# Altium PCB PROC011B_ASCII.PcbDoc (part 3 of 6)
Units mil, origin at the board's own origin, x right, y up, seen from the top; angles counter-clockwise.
Board outline 3304 x 2569 mil, 6 copper layers (TOP, L2-GND1, L3-GND/SIG, L4-GND/SIG, L5-GND2, BOTTOM), stack 55.77 mil thick; 376 components, 289 nets, 1284 pads, 1755 vias.
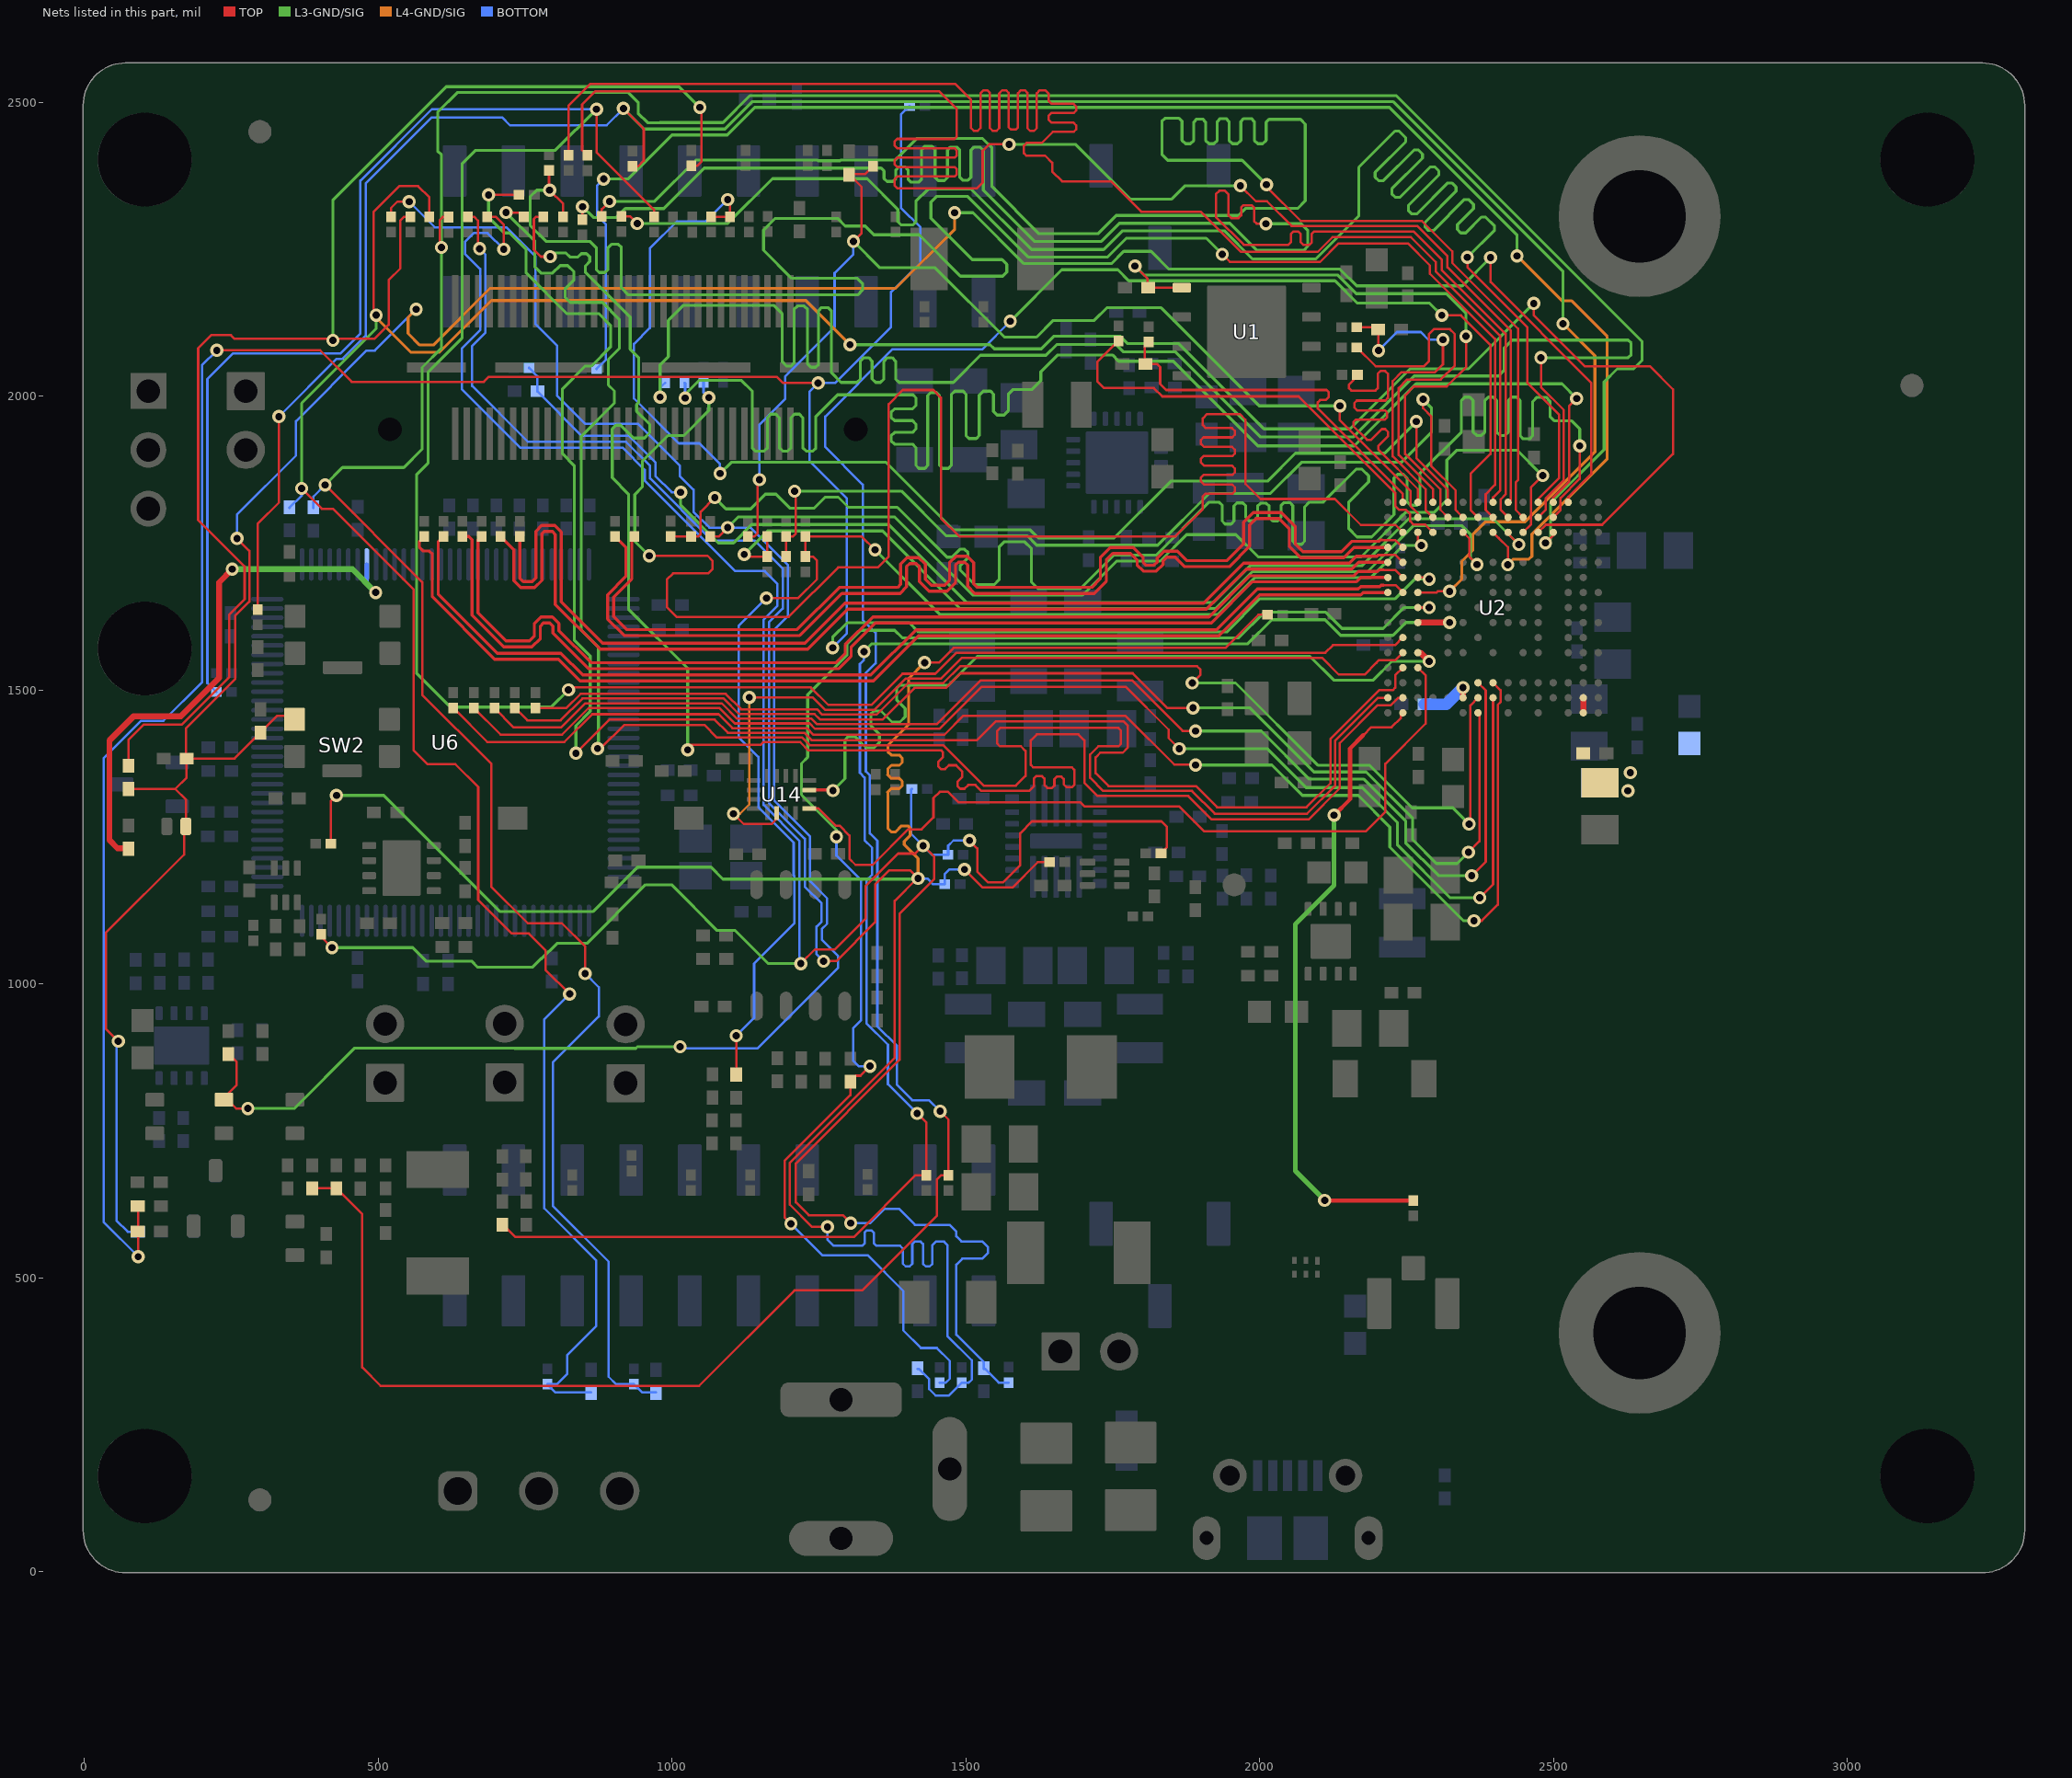
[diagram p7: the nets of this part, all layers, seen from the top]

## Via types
v1: diameter 22.4, hole 12.2, TOP to BOTTOM, tented both sides, 1046 vias
v2: diameter 15.74, hole 5.9, TOP to L2-GND1, tented both sides, 700 vias
v3: diameter 19.68, hole 7.87, TOP to BOTTOM, tented both sides, 9 vias

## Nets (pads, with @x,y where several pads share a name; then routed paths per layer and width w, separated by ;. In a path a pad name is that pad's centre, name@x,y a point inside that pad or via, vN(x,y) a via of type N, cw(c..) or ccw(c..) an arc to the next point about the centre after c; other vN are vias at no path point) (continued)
AR_DMM_SYNC: R55.1 U2.N14 | length 3163.6
  TOP w4: v1(961.35,1728.5) 1060.35,1728.5 1068.85,1720 1068.85,1705.6 1061.75,1698.5 1001.85,1698.5 991.45,1688.1 991.45,1640.9 1007.85,1624.5 1198.75,1624.5 1282.85,1708.6 1350.05,1708.6 1368.75,1727.3 1368.75,1986.5 1392.75,2010.5 1444.75,2010.5 1457.75,1997.5 1457.75,1792.5 1488.85,1761.4 1856.65,1761.4 1903.25,1808 1903.25,1829.61 1907.54,1833.9 1953.46,1833.9 1957.95,1838.39 1957.95,1845.01 1953.06,1849.9 1905.34,1849.9 1900.25,1854.99 1900.25,1861.61 1904.54,1865.9 1953.46,1865.9 1957.95,1870.39 1957.95,1877.01 1953.06,1881.9 1905.34,1881.9 1900.25,1886.99 1900.25,1893.61 1904.54,1897.9 1953.46,1897.9 1957.95,1902.39 1957.95,1909.01 1953.06,1913.9 1905.34,1913.9 1900.25,1918.99 1900.25,1925.61 1904.54,1929.9 1953.46,1929.9 1957.95,1934.39 1957.95,1941.01 1953.06,1945.9 1908.34,1945.9 1903.25,1950.99 1903.25,1962 1910.75,1969.5 1966.55,1969.5 1975.95,1960.1 1975.95,1850.9 2001.75,1825.1 2128.16,1825.1 2172.36,1780.9 2231.21,1780.9 U2.N14@2243.76,1768.35
  L3-GND/SIG w5: v1(961.35,1728.5) 936.75,1753.1 936.75,1832.8 949.65,1845.7 949.65,1889.7 992.95,1933 1020.15,1933 1062.75,1975.6 v1(1062.75,1997.5)
  BOTTOM w4: R55.1@1053.75,2023.31 1053.75,2006.5 v1(1062.75,1997.5)
AR_DP0: R56.1 U2.R4 | length 3155.8
  TOP w4: U2.R4@2499.66,1819.53 2499.66,1827.31 2526.95,1854.6 2526.95,1983.6 v1(2539.55,1996.2)
  L3-GND/SIG w5: v1(1022.45,1997) 1022.45,2002.96 1046.67,2027.18 1117.7,2027.18 1136.75,2008.13 1136.75,1911.51 1141.76,1906.5 1156.74,1906.5 1162.6,1912.36 1162.6,1963.64 1168.46,1969.5 1176.74,1969.5 1182.6,1963.64 1182.6,1912.36 1188.46,1906.5 1196.74,1906.5 1202.6,1912.36 1202.6,1963.64 1208.46,1969.5 1216.74,1969.5 1222.6,1963.64 1222.6,1912.36 1228.46,1906.5 1239.75,1906.5 1244.75,1911.5 1244.75,1965.4 1281.65,2002.3 1410.29,2002.3 1415.29,1997.3 1415.29,1984.27 1409.43,1978.41 1378.61,1978.41 1372.75,1972.55 1372.75,1964.27 1378.61,1958.41 1409.43,1958.41 1415.29,1952.55 1415.29,1944.27 1409.43,1938.41 1378.61,1938.41 1372.75,1932.55 1372.75,1924.27 1378.61,1918.41 1409.43,1918.41 1415.29,1912.55 1415.29,1882.23 1420.29,1877.23 1430.29,1877.23 1435.29,1882.23 1435.29,2001.2 1440.29,2006.2 1450.29,2006.2 1455.29,2001.2 1455.29,1882.23 1460.29,1877.23 1470.29,1877.23 1475.29,1882.23 1475.29,2002.64 1481.15,2008.5 1495.35,2008.5 1500.35,2003.5 1500.35,1933.06 1505.35,1928.06 1517.95,1928.06 1522.95,1933.06 1522.95,2001.7 1529.75,2008.5 1542.25,2008.5 1547.25,2003.5 1547.25,1973.9 1553.15,1968 1565.25,1968 1572.35,1975.1 1572.35,2003.1 1580.75,2011.5 1612.75,2011.5 1627.75,2026.5 1627.75,2041.5 1656.35,2070.1 1749.55,2070.1 1760.15,2059.5 1852.95,2059.5 1996.95,1915.5 2160.95,1915.5 2266.55,2021.1 2514.65,2021.1 v1(2539.55,1996.2)
  BOTTOM w4: R56.1@1021.25,2022.81 1022.45,2021.61 v1(1022.45,1997)
AR_DP1: R57.1 U2.P5 | length 3113.8
  TOP w4: U2.P5@2474.07,1793.94 2486.75,1806.62 2486.75,1826 2517.75,1857 2517.75,1976.5 2478.75,2015.5 v1(2478.75,2065.5)
  L3-GND/SIG w5: v1(979.75,1998.5) 979.75,2053.5 993.75,2067.5 993.75,2128.84 1019.51,2154.6 1172.96,2154.6 1187.72,2139.84 1187.72,2058.36 1194.88,2051.2 1202.72,2051.2 1207.72,2056.2 1207.72,2147.76 1213.54,2153.58 1224.94,2153.58 1230.74,2147.78 1230.74,2055.06 1236.6,2049.2 1244.44,2049.2 1249.44,2054.2 1249.44,2145.78 1254.44,2150.78 1265.65,2150.78 1271.45,2144.98 1271.45,2039.81 1287.76,2023.5 1314.75,2023.5 1320.61,2029.36 1320.61,2059.64 1326.47,2065.5 1334.75,2065.5 1340.61,2059.64 1340.61,2029.36 1346.47,2023.5 1354.75,2023.5 1360.61,2029.36 1360.61,2059.64 1366.47,2065.5 1374.75,2065.5 1380.61,2059.64 1380.61,2029.36 1386.47,2023.5 1478.75,2023.5 1524.75,2069.5 1636.35,2069.5 1654.75,2087.9 1756.15,2087.9 1768.65,2075.4 1856.95,2075.4 2001.85,1930.5 2159.05,1930.5 2263.05,2034.5 2406.75,2034.5 2415.95,2043.7 2415.95,2081.6 2429.85,2095.5 2627.25,2095.5 2632.25,2090.5 2632.25,2070.5 2627.25,2065.5 v1(2478.75,2065.5)
  BOTTOM w4: v1(979.75,1998.5) 979.75,2014.21 R57.1@988.35,2022.81
AR_DP2: R179.1 U2.R5 | length 3176.7
  TOP w4: R179.1@913.75,2305.99 928.76,2305.99 v1(940.85,2293.9) ; v1(2353.55,2236.2) 2353.55,2219.3 2455.75,2117.1 2455.75,2022.5 2509.75,1968.5 2509.75,1861 2474.07,1825.32 U2.R5@2474.07,1819.53
  L3-GND/SIG w5: v1(940.85,2293.9) 1094.95,2293.9 1171.05,2370 1332.25,2370 1384.35,2317.9 1384.35,2296.9 1389.75,2291.5 1410.15,2291.5 1415.15,2296.5 1415.15,2331.7 1435.75,2352.3 1509.15,2352.3 1611.95,2249.5 1734.75,2249.5 1766.75,2281.5 1939.95,2281.5 1987.95,2233.5 2095.75,2233.5 2168.75,2306.5 2168.75,2389.5 2230.41,2451.16 2237.49,2451.16 2248.64,2440.01 2248.64,2432.93 2196.62,2380.91 2196.62,2372.63 2202.49,2366.76 2210.77,2366.76 2263.09,2419.08 2270.17,2419.08 2277.24,2412.01 2277.24,2404.93 2224.92,2352.61 2224.92,2344.33 2230.79,2338.46 2239.07,2338.46 2290.89,2390.28 2297.97,2390.28 2305.04,2383.21 2305.04,2376.13 2253.22,2324.31 2253.22,2316.03 2259.09,2310.16 2267.37,2310.16 2320.04,2362.83 2327.12,2362.83 2334.19,2355.76 2334.19,2348.68 2281.52,2296.01 2281.52,2287.73 2287.39,2281.86 2295.67,2281.86 2348.54,2334.73 2355.62,2334.73 2363.92,2326.43 2363.92,2319.35 2336.55,2291.98 2336.55,2283.7 2342.42,2277.83 2350.7,2277.83 2377.57,2304.7 2384.65,2304.7 2399.81,2289.54 2399.81,2282.46 v1(2353.55,2236.2)
AR_DP3: R180.1 U2.P6 | length 3185.5
  TOP w4: R180.1@880.45,2306.19 880.45,2318.2 v1(893.75,2331.5) ; v1(2011.75,2359.9) 2011.75,2356.5 2070.15,2298.1 2276.15,2298.1 2328.05,2246.2 2328.05,2226.7 2439.75,2115 2439.75,1857.5 2435.75,1853.5 2435.75,1806.67 U2.P6@2448.48,1793.94
  L3-GND/SIG w5: v1(893.75,2331.5) 970.25,2331.5 1040.45,2401.7 1247.75,2401.7 1248.76,2400.69 1285.8,2400.69 1286.81,2401.7 1379.55,2401.7 1416.35,2438.5 1528.75,2438.5 1544.45,2422.8 1544.45,2356.6 1624.65,2276.4 1724.65,2276.4 1755.75,2307.5 1963.75,2307.5 1975.75,2319.5 2064.75,2319.5 2077.75,2332.5 2077.75,2462.9 2069.55,2471.1 2016.07,2471.1 2011.07,2466.1 2011.07,2435.36 2005.21,2429.5 1996.93,2429.5 1991.07,2435.36 1991.07,2467.4 1986.07,2472.4 1973.02,2472.4 1968.02,2467.4 1968.02,2435.36 1962.16,2429.5 1953.88,2429.5 1948.02,2435.36 1948.02,2467.4 1943.02,2472.4 1933.02,2472.4 1928.02,2467.4 1928.02,2435.36 1922.16,2429.5 1913.88,2429.5 1908.02,2435.36 1908.02,2466.6 1903.02,2471.6 1893.02,2471.6 1888.02,2466.6 1888.02,2435.36 1882.16,2429.5 1873.88,2429.5 1868.02,2435.36 1868.02,2467.9 1863.02,2472.9 1838.75,2472.9 1833.75,2467.9 1833.75,2411.5 1843.75,2401.5 1970.15,2401.5 v1(2011.75,2359.9)
AR_DP4: R181.1 U2.R7 | length 2953.5
  TOP w4: R181.1@856.25,2409.79 847.15,2418.89 847.15,2496.5 869.65,2519 1454.08,2519 1484.75,2488.33 1484.75,2441.81 1480.75,2437.81 1383.44,2437.81 1378.75,2433.12 1378.75,2426.5 1383.44,2421.81 1480.74,2421.81 1484.75,2417.8 1484.75,2409.81 1480.75,2405.81 1383.44,2405.81 1378.75,2401.12 1378.75,2394.5 1383.44,2389.81 1480.74,2389.81 1484.75,2385.8 1484.75,2377.81 1480.75,2373.81 1383.44,2373.81 1378.75,2369.12 1378.75,2358.5 1383.75,2353.5 1518.75,2353.5 1528.75,2363.5 1528.75,2417.5 1539.75,2428.5 v1(1573.75,2428.5) ; v1(1967.25,2358.2) 1993.65,2331.8 2012.45,2331.8 2054.45,2289.8 2268.45,2289.8 2319.75,2238.5 2319.75,2219.5 2427.75,2111.5 2427.75,1824.39 U2.R7@2422.89,1819.53
  L3-GND/SIG w5: v1(1573.75,2428.5) 1686.32,2428.5 1779.32,2335.5 1850.45,2335.5 1873.15,2358.2 v1(1967.25,2358.2)
AR_DP5: R182.1 U2.P7 | length 3035.8
  TOP w4: R182.1@847.75,2300.49 v1(847.75,2322.5) ; v1(2010.75,2293.5) 1994.75,2293.5 1990.75,2297.5 1990.75,2320.9 1986.75,2324.9 1972.75,2324.9 1968.75,2320.9 1968.75,2307.6 1964.05,2302.9 1951.95,2302.9 1946.75,2308.1 1946.75,2343.7 1940.85,2349.6 1931.65,2349.6 1925.75,2343.7 1925.75,2304.9 1973.15,2257.5 2048.95,2257.5 2053.64,2262.19 2053.64,2276.3 2057.64,2280.3 2065.64,2280.3 2069.64,2276.3 2069.64,2262.19 2074.33,2257.5 2084.75,2257.5 2088.75,2261.5 2088.75,2276.4 2092.75,2280.4 2261.85,2280.4 2309.75,2232.5 2309.75,2215.1 2418.75,2106.1 2418.75,1833.1 2410.35,1824.7 2410.35,1806.48 U2.P7@2422.89,1793.94
  L3-GND/SIG w5: v1(847.75,2322.5) 866.15,2304.1 905.35,2304.1 920.55,2319.3 986.05,2319.3 1054.95,2388.2 1355.89,2388.2 1360.89,2383.2 1360.89,2370.3 1365.89,2365.3 1375.89,2365.3 1380.89,2370.3 1380.89,2385 1385.89,2390 1396.75,2390 1401.75,2385 1401.75,2369.1 1406.75,2364.1 1419.75,2364.1 1424.75,2369.1 1424.75,2419.9 1429.75,2424.9 1442.75,2424.9 1447.75,2419.9 1447.75,2372.5 1453.25,2367 1463.75,2367 1468.75,2372 1468.75,2418.8 1473.75,2423.8 1484.75,2423.8 1489.75,2418.8 1489.75,2372.6 1494.75,2367.6 1503.75,2367.6 1508.75,2372.6 1508.75,2418.5 1513.75,2423.5 1524.75,2423.5 1529.75,2418.5 1529.75,2350.5 1616.75,2263.5 1730.75,2263.5 1761.55,2294.3 1949.35,2294.3 1995.35,2248.3 2075.41,2248.3 2081.75,2254.64 2081.75,2282.36 2070.61,2293.5 v1(2010.75,2293.5)
AR_DP6: R183.1 U2.R8 | length 2986.4
  TOP w4: R183.1@823.75,2410.19 823.75,2494.2 861.05,2531.5 1481.76,2531.5 1508.89,2504.37 1508.89,2456.19 1513.58,2451.5 1520.2,2451.5 1524.89,2456.19 1524.89,2515.31 1529.98,2520.4 1536.6,2520.4 1540.89,2516.11 1540.89,2456.19 1545.58,2451.5 1552.2,2451.5 1556.89,2456.19 1556.89,2515.31 1561.98,2520.4 1568.6,2520.4 1572.89,2516.11 1572.89,2457.5 1576.89,2453.5 1584.89,2453.5 1588.89,2457.5 1588.89,2515.31 1593.98,2520.4 1600.6,2520.4 1604.89,2516.11 1604.89,2456.19 1609.58,2451.5 1616.2,2451.5 1620.89,2456.19 1620.89,2515.31 1625.98,2520.4 1635.35,2520.4 1640.75,2515 1640.75,2502.6 1645.44,2497.91 1682.76,2497.91 1687.95,2492.72 1687.95,2486.1 1683.76,2481.91 1645.44,2481.91 1640.75,2477.22 1640.75,2470.6 1645.44,2465.91 1682.76,2465.91 1687.95,2460.72 1687.95,2454.1 1683.76,2449.91 1648.15,2449.91 1629.41,2431.17 1603.76,2431.17 1598.85,2426.26 1598.85,2413.2 1602.85,2409.2 1634.95,2409.2 1646.95,2397.2 1646.95,2382.5 1663.85,2365.6 1746.75,2365.6 1798.35,2314 1899.75,2314 1968.25,2245.5 2098.75,2245.5 2123.85,2270.6 2257.65,2270.6 2299.75,2228.5 2299.75,2212.2 2409.75,2102.2 2409.75,1840.1 2397.3,1827.65 U2.R8@2397.3,1819.53
AR_DP7: R60.2 R184.1 U2.P8 | length 3263.4
  TOP w4: R60.2@790.75,2384.51 790.75,2351.5 v1(791.75,2350.5) 814.75,2327.5 R184.1@814.75,2305.49 ; v1(1936.55,2241.4) 1949.45,2228.5 2102.75,2228.5 2134.25,2260 2252.25,2260 2289.75,2222.5 2289.75,2208.5 2400.75,2097.5 2400.75,1849.16 2384.8,1833.21 2384.8,1806.44 U2.P8@2397.3,1793.94
  L3-GND/SIG w5: v1(791.75,2350.5) 769.75,2350.5 758.75,2339.5 758.75,2290.5 785.75,2263.5 860.29,2263.5 871.15,2252.64 871.15,2215.6 876.15,2210.6 886.15,2210.6 891.15,2215.6 891.15,2252.64 897.01,2258.5 908.75,2258.5 913.75,2253.5 913.75,2184.5 925.85,2172.4 1316.05,2172.4 1324.35,2180.7 1324.35,2191.6 1315.45,2200.5 1203.75,2200.5 1155.75,2248.5 1155.75,2282.5 1175.75,2302.5 1281.75,2302.5 1294.75,2289.5 1328.75,2289.5 1343.65,2274.6 1420.65,2274.6 1490.95,2204.3 1563.05,2204.3 1569.85,2211.1 1569.85,2224.4 1561.75,2232.5 1510.85,2232.5 1440.55,2302.8 1440.55,2330.4 1450.05,2339.9 1503.35,2339.9 1606.75,2236.5 1740.75,2236.5 1772.95,2268.7 1909.25,2268.7 v1(1936.55,2241.4)
AR_DP8: R185.1 U2.D14 | length 3016.2
  TOP w4: v1(687.75,2342.5) R185.1@739.76,2342.5 ; v1(836.48,1392.53) 893.6,1449.65 1072.57,1449.65 1094.98,1427.24 1150.34,1427.24 1225.05,1427.23 1237.38,1414.9 1519.15,1414.9 1550.75,1446.5 1768.75,1446.5 1775.45,1439.8 1775.45,1401.8 1767.15,1393.5 1729.05,1393.5 1721.05,1385.5 1721.05,1358.5 1742.95,1336.6 1891.65,1336.6 1927.75,1300.5 2079.75,1300.5 2120.35,1341.1 2120.35,1416.7 2203.45,1499.8 2226.45,1499.8 2230.85,1504.2 2230.85,1525.13 U2.D14@2243.76,1538.04
  L3-GND/SIG w5: v1(687.75,2342.5) 687.75,2304.6 714.51,2277.84 723.51,2277.84 751.75,2249.6 751.75,2209.5 820.75,2140.5 875.75,2140.5 895.55,2120.7 895.55,2083.8 862.95,2051.2 852.15,2051.2 813.65,2012.7 813.65,1901.9 833.75,1881.8 833.75,1585.2 860.95,1558 860.95,1463.76 836.48,1439.29 v1(836.48,1392.53)
AR_DP9: R186.1 U2.B14 | length 3050.2
  TOP w4: R186.1@781.05,2305.49 768.95,2305.49 764.95,2301.49 764.95,2249.3 776.75,2237.5 v1(792.75,2237.5) ; v1(1026.8,1398.19) 1026.8,1406.45 1026.75,1406.5 1026.8,1406.5 1150.55,1406.5 1155.28,1411.23 1218.42,1411.23 1232.45,1397.2 1458.25,1397.2 1460.93,1394.53 1460.93,1385.36 1452.86,1377.3 1452.86,1370.39 1457.75,1365.5 1464.68,1365.5 1471.19,1372.01 1483.44,1372.01 1493.85,1361.61 1493.85,1351.96 1485.78,1343.89 1485.78,1336.98 1490.67,1332.09 1497.6,1332.09 1504.11,1338.6 1516.36,1338.6 1526.46,1328.5 1607.75,1328.5 1616.25,1337 1616.25,1350 1619.75,1353.5 1629.75,1353.5 1633.75,1349.5 1633.75,1338.51 1638.76,1333.5 1646.75,1333.5 1650.75,1337.5 1650.75,1348.5 1654.75,1352.5 1662.75,1352.5 1666.75,1348.5 1666.75,1339.5 1671.75,1334.5 1680.75,1334.5 1684.75,1338.5 1684.75,1364.5 1680.75,1368.5 1614.75,1368.5 1610.75,1372.5 1610.75,1414.5 1620.75,1424.5 1691.75,1424.5 1701.75,1414.5 1701.75,1342.5 1724.55,1319.7 1878.46,1319.7 1918.16,1280 2083.25,1280 2136.35,1333.1 2136.35,1409.9 2200.75,1474.3 2223.35,1474.3 2235.91,1486.86 U2.B14@2243.76,1486.86
  L3-GND/SIG w5: v1(792.75,2237.5) 798.75,2243.5 819.75,2243.5 826.4,2236.85 840.09,2236.85 845.91,2242.67 854.35,2242.67 860.02,2237 860.02,2228.99 852.81,2221.78 852.81,2210.44 928.75,2134.5 928.75,2080 943.15,2065.6 943.15,1989.1 939.75,1985.69 939.75,1974.39 962.19,1951.95 962.19,1937.77 953.26,1928.84 934.64,1928.84 912.69,1950.79 904.83,1950.79 898.25,1944.2 898.25,1861.3 925.95,1833.6 925.95,1637.9 1026.8,1537.05 v1(1026.8,1398.19)
AR_DP10: R187.1 U2.B15 | length 3077.4
  TOP w4: v1(717.75,2312.5) 740.74,2312.5 R187.1@747.75,2305.49 ; v1(873.2,1400.62) 878.75,1400.62 918.91,1440.78 1055.22,1440.78 1076.76,1419.24 1147.03,1419.24 1221.74,1419.23 1234.67,1406.3 1461.75,1406.3 1530.55,1337.5 1585.35,1337.5 1601.75,1353.9 1601.75,1396.5 1593.75,1404.5 1557.95,1404.5 1553.15,1409.3 1553.15,1429.9 1558.75,1435.5 1759.75,1435.5 1764.15,1431.1 1764.15,1408.5 1760.15,1404.5 1725.85,1404.5 1711.75,1390.4 1711.75,1350.6 1733.95,1328.4 1884.85,1328.4 1923.75,1289.5 2080.75,1289.5 2128.35,1337.1 2128.35,1413.3 2201.91,1486.86 U2.B15@2218.17,1486.86
  L3-GND/SIG w5: v1(717.75,2312.5) 766.65,2263.6 766.65,2219.6 776.88,2209.38 796.89,2209.38 809.87,2222.35 822.62,2222.35 833.27,2211.7 833.27,2197.91 818.35,2182.99 818.35,2167.9 826.75,2159.5 881.75,2159.5 910.35,2130.9 910.35,2081 891.75,2062.4 891.75,2019 901.85,2008.9 901.85,1988 845.65,1931.8 845.65,1601.7 874.85,1572.5 874.85,1400.62 874.85,1396.72 873.2,1398.37 v1(873.2,1400.62)
AR_DP11: R188.1 U2.C9 | length 2242.5
  TOP w4: R188.1@697.75,1469.61 730.86,1436.5 811.22,1436.5 852.3,1477.58 1084.64,1477.58 1110.98,1451.24 1170.17,1451.24 ; 1170.18,1451.23 1237.44,1451.23 1246.77,1441.9 1450.75,1441.9 1525.35,1516.5 1783.04,1516.5 1869.14,1430.4 v1(1890.95,1430.4) ; v1(2361.05,1184.3) 2384.75,1208 2384.75,1499.41 U2.C9@2371.71,1512.45
  L3-GND/SIG w5: v1(1890.95,1430.4) 2002.85,1430.4 2084.85,1348.4 2177.65,1348.4 2248.55,1277.5 2248.55,1240.2 2304.45,1184.3 v1(2361.05,1184.3)
AR_DP12: R189.1 U2.C8 | length 2410
  TOP w4: R189.1@627.75,1469.61 685.86,1411.5 816.63,1411.5 864.01,1458.88 1079.2,1458.88 1102.84,1435.24 1155.8,1435.24 1229.65,1435.23 1241.08,1423.8 1463.35,1423.8 1495.95,1456.4 1771.55,1456.4 1854.75,1373.2 1890.35,1373.2 v1(1891.15,1372.4) ; v1(2364.75,1107.5) 2378.05,1107.5 2405.35,1134.8 2405.35,1474.9 2409.95,1479.5 2409.95,1499.8 U2.C8@2397.3,1512.45
  L3-GND/SIG w5: v1(1891.15,1372.4) 2020.85,1372.4 2072.65,1320.6 2168.05,1320.6 2221.65,1267 2221.65,1232.7 2346.85,1107.5 v1(2364.75,1107.5)
AR_DP13: R190.1 U2.B9 | length 2012.7
  TOP w4: R190.1@767.75,1469.61 820.45,1469.61 844.42,1493.58 1091.27,1493.58 1117.61,1467.24 1182.93,1467.24 1246.98,1467.23 1255.81,1458.4 1348.35,1458.4 1401.65,1511.7 1461.65,1511.7 1490.45,1540.5 1893.76,1540.5 1899.4,1534.86 1899.4,1526.15 v1(1885.35,1512.1) ; v1(2356.4,1272.05) 2358.65,1274.3 2358.65,1473.8 U2.B9@2371.71,1486.86
  L3-GND/SIG w5: v1(1885.35,1512.1) 1959.15,1512.1 2099.05,1372.2 2186.85,1372.2 2259.55,1299.5 2328.95,1299.5 v1(2356.4,1272.05)
AR_DP14: R191.1 U2.B8 | length 2323.1
  TOP w4: R191.1@662.75,1469.61 708.36,1424 812.89,1424 858.47,1469.58 1080.56,1469.58 1106.9,1443.24 1164.43,1443.24 1234.12,1443.23 1243.45,1433.9 1455.45,1433.9 1527.05,1505.5 1772.39,1505.5 1845.25,1432.64 1845.25,1418.3 v1(1863.25,1400.3) ; v1(2374.55,1146.6) 2397.3,1169.35 U2.B8@2397.3,1486.86
  L3-GND/SIG w5: v1(1863.25,1400.3) 2012.95,1400.3 2079.25,1334 2174.85,1334 2234.65,1274.2 2234.65,1236.1 2324.15,1146.6 v1(2374.55,1146.6)
AR_DP15: R192.1 U2.A9 | length 2103.2
  TOP w4: R192.1@732.75,1469.61 753.86,1448.5 810.65,1448.5 847.73,1485.58 1087.96,1485.58 1114.3,1459.24 1177.25,1459.24 1242.41,1459.23 1251.74,1449.9 1358.85,1449.9 1412.65,1503.7 1466.45,1503.7 1491.25,1528.5 1783.88,1528.5 1842.78,1469.6 v1(1886.85,1469.6) ; v1(2355.45,1224.1) 2373.95,1242.6 2373.95,1459.03 U2.A9@2371.71,1461.27
  L3-GND/SIG w5: v1(1886.85,1469.6) 1983.66,1469.6 2092.56,1360.7 2181.35,1360.7 2260.55,1281.5 2260.55,1245.2 2300.85,1204.9 2336.25,1204.9 v1(2355.45,1224.1)
AR_GPIO_0: R164.1 R178.2 U2.H13 | length 2684.8
  TOP w4: v1(1202.25,592) 1191.75,602.5 1191.75,698.82 1303.55,810.62 R178.2@1303.55,833.41 1303.55,834.2 1313.15,843.8 1320.75,843.8 v1(1336.95,860) ; U2.H13@2269.35,1640.4 2288.44,1640.4 v1(2288.54,1640.5)
  L3-GND/SIG w5: v1(1279.85,1250.47) 1279.85,1262.26 1220.32,1321.79 1220.32,1375.19 1231,1385.87 1231,1492.31 1297.75,1559.06 1297.75,1578.5 1321.05,1601.8 1379.05,1601.8 1392.05,1588.8 1964.05,1588.8 2007.75,1632.5 2112.65,1632.5 2140.35,1604.8 2210.35,1604.8 2246.05,1640.5 v1(2288.54,1640.5)
  BOTTOM w4: v1(1202.25,592) 1255.75,538.5 1332.76,538.5 1393.75,477.51 1393.75,410.49 1423.74,380.5 1450.75,380.5 1472.75,358.5 1472.75,328.4 1465.58,321.23 R164.1@1455.5,321.23 ; v1(1279.85,1250.47) 1279.85,1218.4 1321.95,1176.3 1321.95,938.4 1308.15,924.6 1308.15,869.5 1317.65,860 v1(1336.95,860)
AR_GPIO_1: R9.2 R72.2 U2.J13 | length 3952.7
  TOP w4: R72.2@295.25,1636.74 295.25,1783.31 331.05,1819.11 v1(331.05,1965.3) ; v1(917.35,2489.6) 951.95,2455 951.95,2400.7 942.48,2391.23 R9.2@932.5,2391.23 ; U2.J13@2269.35,1665.99 2301.18,1665.99 2303.14,1667.95 v1(2323.34,1667.95)
  L3-GND/SIG w5: v1(917.35,2489.6) 952.45,2454.5 1089.95,2454.5 1136.85,2501.4 2226.95,2501.4 2516.35,2212 v1(2516.35,2123.2)
  L4-GND/SIG w5: v1(2323.34,1667.95) 2344.15,1688.76 2344.15,1718.9 2362.75,1737.5 2362.75,1764.6 2384.35,1786.2 2451.65,1786.2 2570.65,1905.2 2570.65,2068.9 v1(2516.35,2123.2)
  BOTTOM w4: v1(331.05,1965.3) 429.25,2063.5 439.55,2063.5 478.85,2102.8 478.85,2362.1 591.25,2474.5 710.75,2474.5 724.35,2460.9 888.65,2460.9 v1(917.35,2489.6)
AR_GPIO_2: R8.2 R110.2 R116.1 U2.K13 | length 4988
  TOP w4: R110.2@91.57,622.27 91.63,622.21 91.63,578.83 v1(91.63,536) ; v1(225.45,2078) 401.45,2078 454.95,2024.5 679.75,2024.5 687.75,2032.5 1178.75,2032.5 1188.75,2022.5 v1(1248.75,2022.5) ; U2.K13@2269.35,1691.58 2285.62,1691.58 v1(2288.5,1688.7)
  L3-GND/SIG w5: v1(1273.45,1572) 1273.45,1590.1 1297.95,1614.6 1403.95,1614.6 1419.75,1598.8 1943.75,1598.8 2000.45,1655.5 2230.75,1655.5 2263.95,1688.7 v1(2288.5,1688.7)
  BOTTOM w4: v1(91.63,536) 32.75,594.88 32.75,1383.6 96.95,1447.8 134.65,1447.8 200.05,1513.2 200.05,2052.6 v1(225.45,2078) ; v1(1273.45,1572) 1297.75,1596.3 1297.75,1825.9 1233.75,1889.9 1233.75,2007.5 v1(1248.75,2022.5) 1277.75,2022.5 1372.75,2117.5 1372.75,2177.5 1422.75,2227.5 1422.75,2287.5 1389.75,2320.5 1389.75,2478.98 R8.2@1404.27,2493.5
AR_HOSTINTR1: R10.2 R13.2 R64.2 U2.P13 | length 1988
  TOP w4: R64.2@1129.36,1761.23 1139.78,1761.23 1145.75,1767.2 1145.75,1855 v1(1148.75,1858) ; v1(1308.75,2263.5) 1322.75,2277.5 1322.75,2356.05 1301.54,2377.26 1301.15,2377.65 1328.42,2377.65 R10.2@1342,2391.23 ; v1(2136.65,1983.5) 2136.65,1958.94 2256.6,1838.99 2256.6,1813.29 2269.35,1800.54 U2.P13@2269.35,1793.94
  L3-GND/SIG w5: v1(1308.75,2263.5) 1353.75,2218.5 1439.55,2218.5 1439.65,2218.6 1447.85,2218.6 1565.95,2100.5 1620.35,2100.5 1648.65,2128.8 1718.35,2128.8 1740.05,2150.5 1832.55,2150.5 1999.55,1983.5 v1(2136.65,1983.5)
  BOTTOM w4: v1(1148.75,1858) 1148.75,1951.4 1192.75,1995.4 1192.75,2033.96 1276.75,2117.96 1276.75,2209.5 1308.75,2241.5 v1(1308.75,2263.5)
AR_LVDS_0_N: R48.2 U2.J15 | length 1868.9
  TOP w5.2: R48.2@578.36,1761.23 570.15,1753.02 570.15,1742.9 576.45,1736.6 586.85,1736.6 592.05,1731.4 592.05,1658.7 698.25,1552.5 806.71,1552.5 843.81,1515.4 1342.65,1515.4 1419.55,1592.3 1930.75,1592.3 2000.24,1661.79 2172.05,1661.79 2176.25,1665.99 U2.J15@2218.17,1665.99
AR_LVDS_0_P: R49.2 U2.J14 | length 1868.8
  TOP w4: 2210.75,1678.49 2231.26,1678.49 U2.J14@2243.76,1665.99
  TOP w5.2: R49.2@611,1761.23 602.25,1752.48 602.25,1662.93 702.48,1562.7 810.94,1562.7 848.04,1525.6 1338.42,1525.6 1415.32,1602.5 1926.53,1602.5 1996.02,1671.99 2167.82,1671.99 2172.02,1676.19 2204.44,1676.19 2206.74,1678.49 2210.75,1678.49
AR_LVDS_1_N: R50.2 U2.K15 | length 1869.9
  TOP w5.2: R50.2@643.5,1761.23 654.54,1761.23 659.75,1756.02 659.75,1627.38 713.63,1573.5 761.75,1573.5 775.95,1587.7 775.95,1609.07 781.18,1614.3 792.15,1614.3 797.55,1608.9 797.55,1596.67 857.82,1536.4 1283.85,1536.4 1304.85,1557.4 1304.85,1572.81 1346.34,1614.3 1917.98,1614.3 1987.98,1684.3 2164.98,1684.3 2172.26,1691.58 U2.K15@2218.17,1691.58
AR_LVDS_1_P: R51.2 U2.K14 | length 1874.4
  TOP w4: 2210.75,1704.5 2230.84,1704.5 U2.K14@2243.76,1691.58
  TOP w5.2: R51.2@676,1761.23 669.95,1755.18 669.95,1631.61 717.86,1583.7 757.52,1583.7 765.75,1591.93 765.75,1613.3 776.95,1624.5 796.38,1624.5 807.75,1613.13 807.75,1600.9 862.05,1546.6 1279.63,1546.6 1294.65,1561.62 1294.65,1577.04 1342.11,1624.5 1913.75,1624.5 1983.75,1694.5 2160.75,1694.5 2168.03,1701.78 2200.73,1701.78 2203.45,1704.5 2210.75,1704.5
AR_LVDS_CLK_N: R52.2 U2.L15 | length 1876.5
  TOP w5.2: R52.2@708.5,1761.23 730.85,1738.88 730.85,1686.07 742.62,1674.3 766.48,1674.3 778.75,1686.57 778.75,1766 782.46,1769.71 796.44,1769.71 801.55,1764.6 801.55,1645.7 877.75,1569.5 1230.78,1569.5 1298.78,1637.5 1909.19,1637.5 1977.19,1705.5 2156.88,1705.5 2168.68,1717.3 2218.04,1717.3 U2.L15@2218.17,1717.17
AR_LVDS_CLK_P: R53.2 U2.L14 | length 1882
  TOP w4: 2210.75,1729.7 2231.23,1729.7 U2.L14@2243.76,1717.17
  TOP w5.2: R53.2@741,1761.23 741,1743.25 741.05,1743.2 741.05,1690.3 746.85,1684.5 762.25,1684.5 768.55,1690.8 768.55,1770.23 778.23,1779.91 800.67,1779.91 811.75,1768.83 811.75,1649.93 881.98,1579.7 1226.55,1579.7 1294.55,1647.7 1904.96,1647.7 1972.96,1715.7 2152.65,1715.7 2164.45,1727.5 2199.95,1727.5 2202.15,1729.7 2210.75,1729.7
AR_LVDS_FRCLK_N: R58.2 U2.M15 | length 1881.7
  TOP w5.2: R58.2@903.3,1761.23 921.35,1743.18 921.35,1693.13 890.45,1662.23 890.45,1620.71 918.46,1592.7 1217.39,1592.7 1289.19,1664.5 1388.22,1664.5 1399.39,1675.67 1399.39,1710.1 1404.59,1715.3 1415.69,1715.3 1420.89,1710.1 1420.89,1684.37 1437.2,1668.06 1468.32,1668.06 1482.51,1682.25 1482.51,1712.5 1487.71,1717.7 1498.11,1717.7 1503.31,1712.5 1503.31,1676.56 1515.37,1664.5 1718.66,1664.5 1739.15,1684.99 1739.15,1721.3 1750.15,1732.3 1780.62,1732.3 1791.63,1721.29 1791.63,1712.75 1802.08,1702.3 1824.48,1702.3 1835.65,1713.47 1835.65,1720.19 1841.76,1726.3 1856.02,1726.3 1872.32,1710 1948.34,1710 1982.95,1744.61 1982.95,1781.1 1993.65,1791.8 2033.02,1791.8 2050.55,1774.27 2050.55,1744.71 2069.76,1725.5 2143.35,1725.5 2160.61,1742.76 U2.M15@2218.17,1742.76
AR_LVDS_FRCLK_P: R59.2 U2.M14 | length 1890.8
  TOP w4: 2208.75,1755.3 2230.85,1755.3 2243.39,1742.76 U2.M14@2243.76,1742.76
  TOP w5.2: R59.2@935.8,1761.23 931.55,1756.98 931.55,1688.9 900.65,1658 900.65,1624.94 922.69,1602.9 1213.16,1602.9 1284.96,1674.7 1383.99,1674.7 1389.19,1679.9 1389.19,1714.33 1400.36,1725.5 1419.92,1725.5 1431.09,1714.33 1431.09,1688.6 1441.43,1678.26 1464.09,1678.26 1472.31,1686.48 1472.31,1716.73 1483.48,1727.9 1502.34,1727.9 1513.51,1716.73 1513.51,1680.79 1519.6,1674.7 1714.43,1674.7 1728.95,1689.22 1728.95,1725.53 1745.92,1742.5 1784.85,1742.5 1801.83,1725.52 1801.83,1716.98 1806.31,1712.5 1820.25,1712.5 1825.45,1717.7 1825.45,1724.42 1837.53,1736.5 1860.25,1736.5 1876.55,1720.2 1944.11,1720.2 1972.75,1748.84 1972.75,1785.33 1989.42,1802 2037.25,1802 2060.75,1778.5 2060.75,1748.94 2073.99,1735.7 2139.12,1735.7 2156.38,1752.96 2203.21,1752.96 2205.55,1755.3 2208.75,1755.3
AR_MCUCLKOUT: R25.1 U2.N8 | length 2820.5
  TOP w4: U2.N8@2397.3,1768.35 2406.85,1758.8 2406.91,1758.8 2422.4,1743.31 v1(2422.4,1713.3)
  L3-GND/SIG w5: v1(883.75,2369.5) 924.95,2369.5 999.85,2444.4 1092.85,2444.4 1092.95,2444.5 1094.15,2444.5 1141.05,2491.4 2220.75,2491.4 2438.15,2274 v1(2438.15,2238.6)
  L4-GND/SIG w5: v1(2422.4,1713.3) 2431.8,1722.7 2458.35,1722.7 2463.35,1727.7 2463.35,1765.4 2591.55,1893.6 2591.55,2101.4 2530.45,2162.5 2514.25,2162.5 v1(2438.15,2238.6)
  BOTTOM w4: R25.1@871.54,2046.3 887.75,2062.51 887.75,2292.5 872.75,2307.5 872.75,2358.5 v1(883.75,2369.5)
AR_MISO1: U2.E14 U14.2 | length 1494.8
  TOP w4: v1(1104.65,1289.46) 1122.21,1271.9 1169.48,1271.9 1178.4,1280.81 U14.2@1178.4,1290.71 ; v1(1131.54,1487.31) 1239.81,1487.31 1260.52,1466.6 1344.75,1466.6 1397.85,1519.7 1457.95,1519.7 1493.25,1555 2106.25,1555 2134.75,1526.5 2178.75,1526.5 2198.75,1546.5 2203.36,1551.1 2231.23,1551.1 U2.E14@2243.76,1563.63
  L4-GND/SIG w4: v1(1104.65,1289.46) 1115.85,1289.46 1131.54,1305.15 v1(1131.54,1487.31)
AR_MOSI1: U2.D13 U14.5 | length 1434.6
  TOP w4: U14.5@1233.51,1298.59 1249.24,1298.59 1278.55,1269.28 1285.36,1269.28 1302.06,1252.58 1302.06,1212.89 1312.36,1202.59 1341.35,1202.59 1401.76,1263 1424.77,1263 1445,1283.23 1445,1316.17 1455.73,1326.9 1469.97,1326.9 1488.07,1308.8 1695.25,1308.8 1701.75,1302.3 1862.95,1302.3 1905.25,1260 2181.25,1260 2213.95,1292.7 2213.95,1374.4 2282.35,1442.8 2282.35,1525.04 U2.D13@2269.35,1538.04
AR_MSS_LOGGER: R26.1 R136.1 U2.F14 | length 4709.3
  TOP w4: v1(823.85,1500.4) 827.96,1504.51 1236.34,1504.51 1266.15,1474.7 1339.35,1474.7 1392.35,1527.7 1447.95,1527.7 1483.85,1563.6 2111.85,1563.6 2124.75,1576.5 2230.35,1576.5 2243.07,1589.22 U2.F14@2243.76,1589.22 ; v1(871.55,2488.4) 871.55,2415.19 969.45,2317.29 R26.1@969.45,2305.09
  L3-GND/SIG w5: v1(823.85,1500.4) 794.35,1470.9 622.85,1470.9 565.65,1528.1 565.65,1866.8 584.75,1885.9 584.75,2040.9 642.65,2098.8 642.65,2395.1 665.95,2418.4 801.55,2418.4 v1(871.55,2488.4)
  BOTTOM w4: R136.1@224.54,1496.79 209.35,1511.98 209.35,2029.3 252.55,2072.5 435.75,2072.5 469.85,2106.6 469.85,2366.61 591.64,2488.4 v1(871.55,2488.4)
AR_NERR_OUT: DS1.2 R19.1 R63.2 R91.1 U2.N6 | length 4879.5
  TOP w4: R91.1@245.27,881.07 245.66,880.68 259.19,867.15 259.19,827.86 237.46,806.13 240.12,806.13 240.27,805.98 258.25,788 v1(278.25,788) ; R19.1@522,2305.21 522,2320.25 532.75,2331 v1(552.75,2331) ; R63.2@1064.86,1761.23 1079.48,1761.23 v1(1094.75,1776.5) ; U2.N6@2448.48,1768.35 2461.55,1781.42 2461.55,1844.7 v1(2481.75,1864.9)
  L3-GND/SIG w5: v1(278.25,788) 357.25,788 460.19,890.94 731.83,890.94 732.5,890.27 938.16,890.27 940.99,893.1 v1(1013.85,893.1) ; v1(1094.75,1776.5) 1112.75,1794.5 1378.85,1794.5 1511.85,1661.5 1698.75,1661.5 1756.75,1719.5 1830.75,1719.5 1875.75,1764.5 1959.75,1764.5 1997.75,1726.5 2172.75,1726.5 2248.75,1802.5 2297.75,1802.5 2318.75,1823.5 2318.75,1891.5 2335.05,1907.8 2438.85,1907.8 v1(2481.75,1864.9)
  BOTTOM w4: v1(552.75,2331) 596.35,2287.4 717.85,2287.4 767.75,2237.5 767.75,2122.5 804.75,2085.5 804.75,2000.5 852.34,1952.91 942.35,1952.91 1013.3,1881.96 1013.3,1864.35 1036.74,1840.91 1036.74,1803.51 1063.75,1776.5 v1(1094.75,1776.5) 1133.75,1776.5 1197.65,1712.6 1197.65,1626.49 1173.92,1602.76 1173.92,1311.81 1235.15,1250.58 1235.15,1174.48 1263.85,1145.78 1263.85,1102.3 1255.05,1093.5 1255.05,1075.2 1282.75,1047.5 1282.75,1027.5 1145.85,890.6 1016.35,890.6 v1(1013.85,893.1)
AR_NERRIN: R16.1 R24.1 U2.N7 | length 2022.6
  TOP w4: U2.N7@2422.89,1768.35 2422.89,1765.91 v1(2441.2,1747.6)
  L3-GND/SIG w5: v1(1014.75,1836.5) 1014.75,1814.5 1078.75,1750.5 1104.75,1750.5 1135.75,1781.5 1368.85,1781.5 1501.55,1648.8 1921.04,1648.8 1983.74,1711.5 2173.75,1711.5 2253.75,1791.5 2397.3,1791.5 v1(2441.2,1747.6)
  BOTTOM w4: R24.1@756.84,2048.1 770.65,2034.29 770.65,2008.5 771.04,2008.11 846.65,1932.5 926.76,1932.5 971.75,1887.51 971.75,1864.4 999.65,1836.5 v1(1014.75,1836.5)
AR_NRST: C11.2 D2.2 R74.1 R77.2 R160.1 SW2.4 U2.R3 | length 4762.2
  TOP w4: v1(57.75,902.5) 36.75,923.5 36.75,1087 169.87,1220.12 D2.2@169.87,1267.97 ; R77.2@75.01,1331.66 154.89,1331.66 ; R74.1@169.87,1379.43 169.87,1380.21 173.3,1383.64 173.3,1435.2 257.05,1518.95 257.05,1626.8 280.75,1650.5 280.75,1737 v1(259.75,1758) ; D2.2@172.72,1267.97 172.72,1313.83 154.89,1331.66 ; SW2.4@357.74,1455.9 327.85,1455.9 255.59,1383.64 R74.1@174.08,1383.64 174.08,1350.86 154.89,1331.66 ; v1(2393.15,2235.9) 2393.15,2194.1 2564.65,2022.6 2564.65,1867.9 2525.25,1828.5 U2.R3@2525.25,1819.53
  L3-GND/SIG w5: v1(1481.05,2312.2) 1512.25,2312.2 1598.95,2225.5 1747.75,2225.5 1768.75,2246.5 1815.25,2246.5 1845.45,2216.3 2136.65,2216.3 2165.15,2187.8 2345.05,2187.8 v1(2393.15,2235.9)
  L4-GND/SIG w5: v1(564.75,2148) 550.95,2134.2 550.95,2106.8 570.75,2087 594.05,2087 690.65,2183.6 1380.85,2183.6 1481.05,2283.8 v1(1481.05,2312.2)
  BOTTOM w4: v1(57.75,902.5) 54.75,899.5 54.75,597.49 73.83,578.41 R160.1@90.76,578.41 R160.1@91.55,578.41 ; v1(259.75,1758) 259.75,1798.5 360.25,1899 360.25,1957.3 480.45,2077.5 494.25,2077.5 v1(564.75,2148)
AR_NRST_MCU: R2.2 R20.1 R77.1 | length 2489.5
  TOP w4: R77.1@75.01,1371.04 75.01,1415.2 101.11,1441.3 166.05,1441.3 246.65,1521.9 246.65,1628.4 272.75,1654.5 272.75,1710.33 193.75,1789.33 193.75,2081.7 215.95,2103.9 249.35,2103.9 255.75,2097.5 423.14,2097.5 v1@425.65,2097.5 ; v1(423.14,2094.99) v1@425.65,2097.5 ; R20.1@554.86,2305.21 543.96,2305.21 537.75,2299 537.75,2217.5 517.75,2197.5 517.75,2121.5 493.75,2097.5 v1@425.65,2097.5 ; R2.2@1032.8,2392.23 1043.48,2392.23 1050.15,2398.9 1050.15,2488.6 v1(1047.35,2491.4)
  L3-GND/SIG w5: v1(423.14,2094.99) 423.14,2333.99 615.75,2526.6 1012.15,2526.6 v1(1047.35,2491.4)
AR_NRST_XDS: R80.1 U6.40 | length 947.4
  TOP w10: R80.1@75.49,1230.75 56.61,1230.75 42.75,1244.61 42.75,1414.3 84.05,1455.6 164.25,1455.6 229.35,1520.7 229.35,1683.3 v1(251.65,1705.6)
  L3-GND/SIG w10: v1(251.65,1705.6) 456.16,1705.6 v1(495.75,1666)
  BOTTOM w7: U6.40@480.68,1713.69 480.68,1681.07 v1(495.75,1666)
AR_OSC_CLKOUT: R111.1 U2.A14 | length 1097.3
  TOP w4: 2176.35,1423.2 2189.75,1436.6 2224.45,1436.6 2240.75,1452.9 2240.75,1458.26 U2.A14@2243.76,1461.27
  TOP w7.08: v1(2110.75,631.66) R111.1@2261.61,631.66 ; v1(2126.75,1287) 2153.95,1314.2 2153.95,1400.8 2176.35,1423.2
  L3-GND/SIG w8: v1(2110.75,631.66) 2060.75,681.66 2060.75,1101.5 2126.75,1167.5 v1(2126.75,1287)
AR_PMIC_CLKOUT_SOP2: R97.1 R98.1 R109.2 U2.P9 | length 4569
  TOP w4: R97.1@387.75,652.75 428.57,652.75 428.96,652.36 472.75,608.57 472.75,347.49 504.24,316 1045.95,316 1208.45,478.5 1323.74,478.5 1450.55,605.31 1450.55,666.8 1458.32,674.57 R109.2@1470.6,674.57 1470.6,769.05 v1(1456.3,783.35) ; v1(2310.05,2137.6) 2342.65,2137.6 2392.75,2087.5 2392.75,1901.6 2359.21,1868.06 2359.21,1806.44 U2.P9@2371.71,1793.94
  L3-GND/SIG w5: v1(1575.75,2127.5) 1663.35,2215.1 1758.75,2215.1 1777.45,2196.4 1798.75,2196.4 1798.85,2196.3 2128.25,2196.3 2166.15,2158.4 2289.25,2158.4 v1(2310.05,2137.6)
  BOTTOM w4: v1(1456.3,783.35) 1437.45,802.2 1408.85,802.2 1382.85,828.2 1382.85,894.3 1349.53,927.62 1349.53,1243.34 1336.71,1256.16 1336.71,1354.9 1329.95,1361.66 1329.95,1529 1346.45,1545.5 1346.45,1597.6 1324.75,1619.3 1324.75,1849.6 1260.75,1913.6 1260.75,1965.5 1374.75,2079.5 1527.75,2079.5 v1(1575.75,2127.5)
AR_QSPI_CS: R38.1 U1.1 U2.P11 | length 1151.8
  TOP w4: v1(1787.9,2221.45) 1809.45,2199.9 1809.45,2184.34 1809.79,2184.68 1810.24,2184.68 U1.1@1865.68,2184.68 ; U2.P11@2320.53,1793.94 2307.75,1806.72 2307.75,1841.5 2247.75,1901.5 2247.75,2001.5 2262.75,2016.5 2318.65,2016.5 2351.25,2049.1 v1(2351.25,2101.9)
  L3-GND/SIG w5: v1(1787.9,2221.45) 1803.05,2206.3 2132.45,2206.3 2164.35,2174.4 2317.65,2174.4 2351.25,2140.8 v1(2351.25,2101.9)
AR_QSPI_D0: R45.2 U2.R13 | length 603.5
  TOP w4: R45.2@2166.42,2036.35 2159.45,2029.38 2159.45,2027.2 2152.05,2019.8 2152.05,2013.6 2156.05,2009.6 2197.05,2009.6 2201.05,2013.6 2201.05,2038.3 2205.65,2042.9 2213.75,2042.9 2218.35,2038.3 2218.35,1997 2213.85,1992.5 2165.35,1992.5 2161.35,1988.5 2161.35,1980.49 2166.04,1975.8 2213.15,1975.8 2217.15,1971.8 2217.15,1964.2 2213.15,1960.2 2163.85,1960.2 2159.85,1956.2 2159.85,1948.9 2182.85,1925.9 2189.81,1925.9 2207.91,1944 2213.59,1944 2218.65,1938.94 2218.65,1932.1 2202.22,1915.67 2202.22,1909.03 2269.35,1841.9 U2.R13@2269.35,1819.53
AR_QSPI_D1: R39.1 U2.N12 | length 781.1
  TOP w4: R39.1@1759.65,2094.01 1723.75,2058.11 1723.75,2025.2 1735.15,2013.8 1820.15,2013.8 1834.35,1999.6 2066.65,1999.6 2230.75,1835.5 2230.75,1813.5 2237.25,1807 2248.45,1807 2256.35,1799.1 2256.35,1787.2 2262.15,1781.4 2281.89,1781.4 U2.N12@2294.94,1768.35
AR_QSPI_D2: R42.1 R43.1 U2.R14 | length 650.6
  TOP w4: R42.1@1811.25,2092.31 1804.85,2085.91 1804.85,2054.5 R43.1@1805.64,2054.5 1825.95,2054.5 1830.75,2049.7 1830.75,2020.8 1841.05,2010.5 2113.75,2010.5 2117.75,2006.5 2117.75,1999 2112.25,1993.5 2102.75,1993.5 2098.85,1989.6 2098.85,1978.9 2243.76,1833.99 U2.R14@2243.76,1819.53
AR_QSPI_D3: R40.2 R41.1 U2.P12 | length 601.8
  TOP w4: R40.2@2165.42,2117.35 2198.53,2117.35 2202.01,2113.87 2202.4,2113.48 v1(2202.4,2077.65) ; U2.P12@2294.94,1793.94 2294.85,1793.94 2282.35,1806.44 2282.35,1841.9 2226.65,1897.6 2226.65,2025.8 2241.65,2040.8 2298.65,2040.8 2312.05,2054.2 v1(2312.05,2096.2)
  BOTTOM w4: v1(2202.4,2077.65) 2233.88,2109.13 2274.31,2109.13 2287.24,2096.2 v1(2312.05,2096.2)
AR_QSPI_SCLK: R44.2 U2.R12 | length 619.7
  TOP w4: R44.2@2165.42,2082.85 2197.37,2050.9 2279.68,2050.9 2287.95,2059.17 2287.95,2105.2 2296.65,2113.9 2323.84,2113.9 2332.15,2105.59 2332.15,2052 2308.35,2028.2 2251.05,2028.2 2236.75,2013.9 2236.75,1900.2 2294.94,1842.01 U2.R12@2294.94,1819.53
AR_RS232RX: R33.1 R129.1 R166.1 R172.1 U2.N4 | length 5540.3
  TOP w4: v1(409.75,1849) 575.15,1683.6 575.15,1491.7 692.81,1374.04 692.81,1164.84 754.49,1103.17 812.43,1103.17 852.25,1063.35 v1(852.25,1017.5) ; v1(607.75,2253) 604.75,2256 604.75,2299.63 609.89,2304.77 R33.1@620.14,2304.77 ; v1(2486.55,1750.5) 2499.66,1763.61 U2.N4@2499.66,1768.35
  L3-GND/SIG w5: v1(409.75,1849) 439.35,1878.6 543.65,1878.6 574.75,1909.7 574.75,2048.9 607.75,2081.9 v1(607.75,2253) 607.75,2410.6 601.25,2417.1 601.25,2483.2 634.65,2516.6 925.85,2516.6 942.45,2500 942.45,2481.3 958.35,2465.4 979.15,2465.4 979.2,2465.45 1086.7,2465.45 1132.65,2511.4 2232.55,2511.4 2650.85,2093.1 2650.85,2061 2636.35,2046.5 2608.55,2046.5 2586.15,2024.1 2586.15,1909.1 2495.09,1818.04 2495.09,1755.5 2490.09,1750.5 v1(2486.55,1750.5)
  BOTTOM w4: R129.1@389.75,1809.9 R129.1@389.75,1810.68 389.75,1829 v1(409.75,1849) ; v1(852.25,1017.5) 875.35,994.4 875.35,944.6 797.75,867 797.75,621.89 892.15,527.49 892.15,331.6 904.96,318.79 R166.1@935.5,318.79 949.54,304.75 R172.1@972.93,304.75
AR_RS232TX: R21.1 R128.1 R169.1 R173.1 U2.N5 | length 5606.2
  TOP w4: v1(369.75,1843) 404.25,1808.5 423.15,1808.5 560.25,1671.4 560.25,1397.88 584.41,1373.72 631.53,1373.72 670.31,1334.94 670.31,1142.86 727.39,1085.79 756.43,1085.79 784.85,1057.37 784.85,1023.9 v1(825.85,982.9) ; v1(496.55,2137.88) 492.37,2137.88 492.37,2314.11 535.76,2357.5 567.75,2357.5 587.1,2338.15 R21.1@587.1,2305.21 ; v1(2466.45,2157.8) 2466.45,2137.8 2553.15,2051.1 2664.15,2051.1 2703.55,2011.7 2703.55,1901.8 2583.05,1781.3 2487.02,1781.3 U2.N5@2474.07,1768.35
  L3-GND/SIG w5: v1(369.75,1843) 369.75,1988 496.55,2114.8 v1(496.55,2137.88) ; v1(1302.95,2087.6) 1541.25,2087.6 1548.35,2080.5 1628.75,2080.5 1650.45,2102.2 1762.75,2102.2 1775.55,2089.4 1862.55,2089.4 2007.45,1944.5 2153.95,1944.5 2255.95,2046.5 2355.15,2046.5 v1(2466.45,2157.8)
  L4-GND/SIG w5: v1(496.55,2137.88) 496.55,2133.7 555.55,2074.7 604.45,2074.7 692.55,2162.8 1227.75,2162.8 v1(1302.95,2087.6)
  BOTTOM w4: R128.1@349.25,1810.25 349.64,1810.64 369.75,1830.75 v1(369.75,1843) ; v1(825.85,982.9) 782.75,939.8 782.75,618 871.25,529.5 871.25,417.99 821.75,368.49 821.75,336.8 803.74,318.79 R169.1@787.88,318.79 801.92,304.75 R173.1@862.63,304.75
AR_SCL: R5.1 R22.1 R146.1 R163.1 R171.1 R198.1 R210.1 | length 6115.8
  TOP w4: R198.1@419.34,1238.3 419.34,1310.89 v1(429.05,1320.6) ; R22.1@652.86,2305.21 663.11,2305.21 669.85,2298.47 669.85,2253.9 v1(672.75,2251) ; v1(1257.95,1038.7) 1279.75,1038.7 1345.95,1104.9 1345.95,1169.31 1369.88,1193.24 1404.97,1193.24 1417.98,1180.23 1379.05,1141.3 1379.05,874.12 1200.75,695.82 1200.75,624.3 1238.55,586.5 v1(1264.75,586.5) ; v1(1429.95,1546.7) 1454.15,1546.7 1479.15,1571.7 1941.55,1571.7 1998.14,1628.29 R210.1@2013.49,1628.29 ; v1(1497.75,1194.9) 1528.55,1164.1 1579.35,1164.1 1622.25,1207 R5.1@1642.66,1207
  L3-GND/SIG w5: v1(429.05,1320.6) 509.55,1320.6 706.85,1123.3 866.06,1123.3 941.46,1198.7 1066.35,1198.7 1086.65,1178.4 1417.85,1178.4 v1(1418.83,1179.38)
  L4-GND/SIG w5: 1367.23,1326.21 1367.3,1326.28 ; 1367.23,1355.73 1367.3,1355.66 ; v1(1418.83,1179.38) 1418.83,1213.28 1395.21,1236.89 1395.21,1242.72 1405.34,1252.85 1405.34,1264.93 1401.4,1268.87 1390.58,1268.87 1380.09,1258.38 1373.72,1258.38 1367.3,1264.81 1367.3,1326.28 ; v1(1429.95,1546.7) 1402.75,1519.5 1402.75,1441.1 1367.3,1405.65 1367.3,1395.29 1373.17,1389.42 1386.69,1389.42 1391.79,1384.32 1391.79,1376.76 1387.08,1372.05 1373.58,1372.05 1367.3,1365.77 1367.3,1355.66 ; 1367.3,1326.28 1373.51,1332.49 1387.01,1332.49 1391.72,1337.2 1391.72,1344.76 1386.62,1349.86 1373.1,1349.86 1367.3,1355.66
  BOTTOM w4: v1(672.75,2251) 682.75,2241 682.75,2108.5 659.75,2085.5 659.75,2017.5 754.75,1922.5 921.75,1922.5 962.75,1881.5 962.75,1860 1068.65,1754.1 1141.15,1754.1 1188.65,1706.6 1188.65,1638.8 1164.92,1615.07 1164.92,1308.08 1226.15,1246.85 1226.15,1165.49 1254.55,1137.09 1254.55,1105.8 1246.05,1097.3 1246.05,1050.6 v1(1257.95,1038.7) ; v1(1264.75,586.5) 1264.75,564.7 1274.95,554.5 1323.74,554.5 1327.75,558.51 1327.75,576.7 1331.75,580.7 1339.54,580.7 1343.75,576.49 1343.75,558.5 1347.75,554.5 1388.25,554.5 1392.94,549.81 1392.94,524.09 1397.63,519.4 1404.25,519.4 1408.94,524.09 1408.94,557.4 1412.94,561.4 1423.32,561.4 1427.32,557.4 1427.32,524.09 1432.01,519.4 1438.63,519.4 1443.32,524.09 1443.32,555.66 1449.06,561.4 1463.05,561.4 1468.75,555.7 1468.75,401.01 1510.35,359.41 1510.35,326.83 1504.75,321.23 R163.1@1493,321.23 1471.51,299.74 1448.51,299.74 1437.75,310.5 1437.75,327.4 1419.9,345.25 R171.1@1418.12,345.25 ; v1(1418.83,1179.38) 1434.67,1179.38 1444.55,1169.5 R146.1@1464.36,1169.5 1464.36,1187.21 1472.05,1194.9 v1(1497.75,1194.9)
AR_SDA: R23.1 R144.2 R162.1 R168.2 R170.1 R199.2 R211.1 | length 5223.1
  TOP w4: R199.2@403.05,1084.31 403.05,1080.1 v1(421.55,1061.6) ; R23.1@685.36,2305.21 700.04,2305.21 713.75,2291.5 v1(713.75,2250) ; v1(1219.15,1034.5) 1243.45,1058.8 1277.45,1058.8 1329.5,1110.85 1329.5,1166.5 1384.75,1221.75 1413.95,1221.75 v1(1427.37,1235.17) 1446.25,1216.29 1446.25,1178.6 1387.15,1119.5 1387.15,870.9 1210.75,694.5 1210.75,628.61 1232.86,606.5 1290.75,606.5 v1(1304.25,593) ; v1(1506.45,1244.07) 1506.45,1243.8 1519.65,1230.6 1519.65,1191.2 1538.35,1172.5 1563.04,1172.5 1592.55,1202.01 1592.55,1256.3 1612.75,1276.5 1833.14,1276.5 1842.05,1267.59 1842.05,1232.11 R168.2@1832.34,1222.4
  L3-GND/SIG w5: v1(421.55,1061.6) 558.75,1061.6 581.55,1038.8 659.05,1038.8 669.55,1028.3 762.45,1028.3 776.95,1042.8 778.15,1042.8 804.35,1069 855.35,1069 955.01,1168.66 999.45,1168.66 1037.45,1130.66 1037.45,1130.19 1076.79,1090.85 1107.71,1090.85 1164.06,1034.5 v1(1219.15,1034.5)
  BOTTOM w4: v1(713.75,2250) 686.25,2277.5 662.75,2277.5 647.75,2262.5 647.75,2242.5 673.75,2216.5 673.75,2112.5 642.75,2081.5 642.75,2011.5 741.75,1912.5 915.75,1912.5 953.75,1874.5 953.75,1863.8 953.65,1863.7 953.65,1856.3 1107.45,1702.5 1157.75,1702.5 1179.65,1680.6 1179.65,1643.6 1155.92,1619.87 1155.92,1304.36 1217.15,1243.13 1217.15,1036.5 v1(1219.15,1034.5) ; v1(1304.25,593) 1337.45,593 1361.95,617.5 1386.15,617.5 1413.65,590 1472.2,590 1483.75,578.45 1483.75,570.43 1492.38,561.8 1528.27,561.8 1537.97,552.1 1537.97,542.78 1527.72,532.53 1494.11,532.53 1483.75,522.17 1483.75,403 1530.77,355.98 R170.1@1530.77,346.04 1530.77,345.25 1532.49,345.25 1555.95,321.79 R162.1@1573,321.79 ; R211.1@1408.17,1331.73 1407.05,1330.61 1407.05,1255.49 v1(1427.37,1235.17) 1442.94,1219.6 R144.2@1469.76,1219.6 1470.06,1219.6 1470.06,1235.11 1479.02,1244.07 v1(1506.45,1244.07)
AR_SPICLK1: U2.E13 U14.7 | length 1373.8
  TOP w5: U14.7@1233.51,1330.08 1272.86,1330.08 v1(1274.01,1328.93)
  TOP w10: U2.E13@2269.35,1563.63 2273.63,1563.63 v1(2288.46,1548.8)
  L3-GND/SIG w5: v1(1274.01,1328.93) 1294.43,1349.35 1294.43,1415.08 1299.93,1420.59 1311.84,1420.59 1330.71,1401.72 1344.05,1401.72 1353.12,1410.79 1353.12,1423.66 1353.6,1424.14 1338.32,1439.42 1338.32,1458.98 1343.72,1464.37 1355.7,1464.37 1374.57,1445.5 1387.91,1445.5 1396.98,1454.57 1396.98,1468.4 1382.18,1483.2 1382.18,1502.76 1387.55,1508.13 1387.55,1508.2 1470.56,1508.2 1519.86,1557.5 2085.36,1557.5 2125.86,1517 2193.35,1517 2225.15,1548.8 v1(2288.46,1548.8)
AR_SYNC_IN: R62.2 R165.1 U2.P4 | length 3219.4
  TOP w4: R165.1@997.75,1761.51 1032.32,1761.51 R62.2@1032.6,1761.23 1044.08,1761.23 1048.75,1765.9 1048.75,1803.5 v1(1072.75,1827.5) ; U2.P4@2499.66,1793.94 2512.25,1806.53 2512.25,1826.82 2544.75,1859.32 v1(2544.75,1915.5)
  L3-GND/SIG w5: v1(1072.75,1827.5) 1091.85,1808.4 1133.95,1808.4 1158.95,1833.4 1176.85,1833.4 1201.05,1809.2 1241.45,1809.2 1260.45,1828.2 1282.95,1828.2 1300.15,1811 1383.25,1811 1468.04,1726.21 1476.32,1726.21 1489.69,1739.58 1497.97,1739.58 1503.84,1733.71 1503.84,1725.43 1490.47,1712.06 1490.47,1703.78 1514.75,1679.5 1548.75,1679.5 1556.75,1687.5 1556.75,1743.5 1565.75,1752.5 1599.75,1752.5 1611.75,1740.5 1611.75,1683.5 1622.75,1672.5 1694.75,1672.5 1751.75,1729.5 1823.65,1729.5 1913.55,1819.4 1931.45,1819.4 1936.45,1814.4 1936.45,1787.45 1941.45,1782.45 1951.41,1782.45 1956.45,1787.49 1956.45,1813.3 1961.45,1818.3 1971.45,1818.3 1976.45,1813.3 1976.45,1793.91 1982.31,1788.05 1990.59,1788.05 1996.45,1793.91 1996.45,1812.9 2001.45,1817.9 2011.45,1817.9 2016.45,1812.9 2016.45,1793.91 2022.31,1788.05 2030.59,1788.05 2036.45,1793.91 2036.45,1813.9 2041.45,1818.9 2051.45,1818.9 2056.45,1813.9 2056.45,1753.05 2061.45,1748.05 2071.45,1748.05 2076.45,1753.05 2076.45,1811.4 2084.85,1819.8 2108.05,1819.8 2164.05,1875.8 2174.35,1875.8 2185.76,1864.39 2185.76,1854.21 2151.75,1820.2 2151.75,1774.5 2165.75,1760.5 2190.75,1760.5 2228.75,1798.5 2228.75,1860.9 2234.75,1866.9 2244.75,1866.9 2250.75,1860.9 2250.75,1820.49 2256.74,1814.5 2267.75,1814.5 2272.75,1819.5 2272.75,1868.5 2343.41,1939.16 2343.41,1992.64 2349.27,1998.5 2357.55,1998.5 2363.41,1992.64 2363.41,1939.16 2369.27,1933.3 2377.55,1933.3 2383.41,1939.16 2383.41,1992.64 2389.27,1998.5 2397.55,1998.5 2403.41,1992.64 2403.41,1939.16 2409.27,1933.3 2417.55,1933.3 2423.41,1939.16 2423.41,1992.64 2429.27,1998.5 2437.55,1998.5 2443.41,1992.64 2443.41,1932.54 2448.45,1927.5 2459.65,1927.5 2464.65,1932.5 2464.65,1990.7 2472.05,1998.1 2487.65,1998.1 2494.25,1991.5 2494.25,1965.3 2501.25,1958.3 2530.55,1958.3 2544.75,1944.1 v1(2544.75,1915.5)
AR_SYNC_OUT_SOP1: R108.2 R113.1 U2.G13 | length 2815.8
  TOP w4: R113.1@711.67,591.15 712.06,590.76 733.52,569.3 1309.54,569.3 1414.81,674.57 R108.2@1433.1,674.57 1433.1,763.85 v1(1417.3,779.65)
  TOP w10: U2.G13@2269.35,1614.81 2305.01,1614.81 2305.1,1614.9 v1(2323.3,1614.9)
  L3-GND/SIG w5: v1(1326.75,1565.5) 1340.05,1578.8 1980.05,1578.8 2020.85,1619.6 2111.35,1619.6 2137.85,1593.1 2226.95,1593.1 2248.75,1614.9 v1(2323.3,1614.9)
  BOTTOM w4: v1(1326.75,1565.5) 1326.75,1551.2 1319.75,1544.2 1319.75,1359.13 1327.71,1351.17 1327.71,1244.52 1340.53,1231.7 1340.53,1185.67 1330.95,1176.09 1330.95,933.2 1367.55,896.6 1367.55,829.4 v1(1417.3,779.65)
AR_TCK: R66.2 R70.1 U2.P10 | length 1617.8
  TOP w4: R70.1@1194.08,1727.21 1194.5,1727.63 R66.2@1194.5,1761.23 1205.48,1761.23 1210.75,1766.5 1210.75,1836.5 v1(1208.75,1838.5) ; v1(2278.15,1994.7) 2278.15,1979.6 2292.35,1965.4 2292.35,1880.9 2333.55,1839.7 2333.55,1806.54 2336.44,1803.65 2336.44,1803.55 2346.05,1793.94 U2.P10@2346.12,1793.94
  L3-GND/SIG w5: v1(1208.75,1838.5) 1390.35,1838.5 1466.35,1762.5 1604.75,1762.5 1620.75,1746.5 1826.45,1746.5 1914.45,1834.5 2018.15,1834.5 2071.15,1887.5 2241.45,1887.5 2292.35,1938.4 2292.35,1980.5 v1(2278.15,1994.7)
AR_TDI: R29.1 R30.1 U2.R11 | length 2192.5
  TOP w4: R29.1@1066.58,2305.21 R30.1@1098.5,2305.21 1098.5,2330.75 v1(1094.75,2334.5) ; v1(2266.75,1956.9) 2266.75,1894.5 2320.53,1840.72 U2.R11@2320.53,1819.53
  L3-GND/SIG w5: v1(1081.75,1868.5) 1100.75,1887.5 1364.35,1887.5 1479.35,1772.5 1609.75,1772.5 1623.75,1758.5 1752.05,1758.5 1849.05,1855.5 2013.35,1855.5 2060.85,1903 2212.85,1903 v1(2266.75,1956.9)
  BOTTOM w4: v1(1081.75,1868.5) 1081.75,1884.5 1046.48,1919.77 1011.72,1919.77 935.45,1996.04 935.45,2089.06 962.51,2116.12 962.51,2251.26 1008.75,2297.5 1057.75,2297.5 v1(1094.75,2334.5)
AR_TDO_SOP0: R67.2 R71.1 R89.1 U2.N13 | length 2275.2
  TOP w4: v1(1109.25,911.8) 1109.33,911.72 R89.1@1109.33,845.74 R89.1@1109.33,844.95 ; v1(1160.75,1656.5) 1214.75,1656.5 1246.75,1688.5 1246.75,1720.5 1240.04,1727.21 R71.1@1227.08,1727.21 1227,1727.29 R67.2@1227,1761.23 1323.02,1761.23 v1(1345.65,1738.6) ; U2.N13@2269.35,1768.35 2269.35,1752 v1(2275.25,1746.1)
  L3-GND/SIG w5: v1(1345.65,1738.6) 1455.45,1628.8 1929.45,1628.8 1992.15,1691.5 2189.55,1691.5 2244.15,1746.1 v1(2275.25,1746.1)
  BOTTOM w4: v1(1109.25,911.8) 1139.75,942.3 1139.75,1034.5 1208.15,1102.9 1208.15,1183.39 1207.05,1184.49 1207.05,1240.5 1146.92,1300.63 1146.92,1386.08 1113.84,1419.16 1113.84,1609.59 v1(1160.75,1656.5)
AR_TMS: R65.2 R69.1 U2.N10 | length 1566.1
  TOP w4: v1(1123.11,1730.85) 1126.75,1727.21 R69.1@1162,1727.21 R65.2@1162,1761.23 ; U2.N10@2346.12,1768.35 2357.07,1757.4 2357.07,1726.57 v1(2369.94,1713.7)
  L3-GND/SIG w5: v1(1123.11,1730.85) 1162.86,1770.6 1358.45,1770.6 1490.25,1638.8 1925.25,1638.8 1987.95,1701.5 2183.75,1701.5 2261.75,1779.5 2344.75,1779.5 2358.75,1765.5 2358.75,1724.89 v1(2369.94,1713.7)
AR_VBGAP: C56.2 U2.B10 | length 95.2
  TOP w10: U2.B10@2346.12,1486.86 v1(2346.12,1504.3)
  BOTTOM w20: C56.2@2280.2,1475.8 C56.2@2280.59,1475.8 2317.62,1475.8 v1(2346.12,1504.3)
AR_VOUT_PA: C10.2 C65.2 C83.2 R137.2 U2.A2 U2.B2 | length 44.9
  TOP w10: U2.A2@2550.84,1461.27 U2.B2@2550.84,1486.86 ; C83.2@2579.15,1342.15 C83.2@2592.8,1328.5
  other v1: 2626.75,1328.5 2630.75,1359.5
